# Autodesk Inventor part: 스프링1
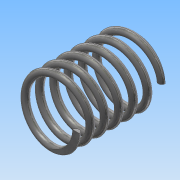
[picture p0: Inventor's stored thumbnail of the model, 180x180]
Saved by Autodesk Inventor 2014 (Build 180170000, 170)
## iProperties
Created: 2019-07
Part Number: 스프링1
Material: 강철, 탄소
Document SubType Name: Modeling
Designer: net
Density: 7.87 g/cm^3
Appearance: 반연마
Mass: 7.79005 g
Surface Area: 20.0872 cm^2
Volume: 0.989841 cm^3
Author: net
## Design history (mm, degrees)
sketch "스케치1"
  geometry: L1 (0, 0)-(8.5, 0); L2 (8.5, 0)-(8.5, 25.33); L3 (8.5, 25.33)-(0, 25.33); L4 (0, 25.33)-(0, 0); C1 r 1 at (8.5, 0)
  constraints: 8 end point, 2 parallel, 1 centre point, 1 coincident, 1 horizontal, 1 perpendicular
  dimensions: "d0" = 17 diameter of L2 L4; "d1" = 25.33013 distance of L1.end L2.end (derived); "d2" = 2 diameter of C1
feature "코일1" pitch "d3" = 10; turns "d5" = 6; dims "d4" = 25.33013 (= d1), "d6" = 0, angle "d7" = 90 deg, angle "d8" = 90 deg, "d9" = 0, "d10" = 0
node "작업 평면1"
node "작업 평면2"
sketch "스케치2"
  geometry: L1 (-1, 0)-(1, 0) reference; 1 further point
  constraints: 1 horizontal alignment
extrude "돌출1" cut sketch "스케치2" stored distance "d13" = 10; taper "d14" = 0 deg
sketch "스케치3"
  geometry: L1 (7.5, 0)-(9.5, 0) reference; 1 further point
  constraints: 1 horizontal alignment
extrude "돌출2" cut sketch "스케치3" stored distance "d15" = 10; taper "d16" = 0 deg
node "솔리드1"
node "절단 모서리 투영1"
node "절단 모서리 투영2"
other parameters: "d11" = 90 deg, "d12" = 90 deg
